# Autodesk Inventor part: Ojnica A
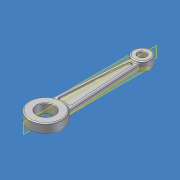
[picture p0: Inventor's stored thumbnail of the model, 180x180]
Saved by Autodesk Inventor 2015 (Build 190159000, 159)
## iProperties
Created: 2009-03
Part Number: Ojnica A
Document SubType Name: Modeling
Designer: Skola
Material: Všeobecné
Density: 1 g/cm^3
Mass: 13.4825 g
Surface Area: 73.0782 cm^2
Volume: 13.4825 cm^3
Appearance: Výchozí
Author: Skola
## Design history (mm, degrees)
sketch "Náčrt1"
  geometry: L1 (-69.019, -110.641)-(-63.941, -31.492); L2 (-53.491, -31.492)-(-48.413, -110.641); C1 r 4 at (-58.716, -24.164); C2 r 9 at (-58.716, -124.164); A1 r 17 centre (-58.716, -124.164) between (-69.019, -110.641) and (-48.413, -110.641); A2 r 9 centre (-58.716, -24.164) between (-53.491, -31.492) and (-63.941, -31.492)
  constraints: 4 centre point, 4 end point, 4 point on circle, 2 coincident
  dimensions: "d0" = 34 diameter of A1; "d1" = 18 diameter of A2; "d2" = 8 diameter of C1; "d3" = 18 diameter of C2; "d4" = 100 distance of A1.centre A2.centre
extrude "Vysunutí1" new body sketch "Náčrt1" distance "d5" = 6; taper "d6" = 0 deg
sketch "Náčrt2"
  geometry: C1 r 9 at (-58.716, -124.164) reference; C2 r 4 at (-58.716, -24.164) reference; C3 r 9 at (-58.716, -24.164); C4 r 17 at (-58.716, -124.164); A1 r 17 centre (-58.716, -124.164) between (-69.019, -110.641) and (-48.413, -110.641) reference; A2 r 9 centre (-58.716, -24.164) between (-53.491, -31.492) and (-63.941, -31.492) reference
  constraints: 2 centre point, 2 coincident, 2 concentric
extrude "Vysunutí2" join sketch "Náčrt2" distance "d7" = 2; taper "d8" = 0 deg
sketch "Náčrt3"
  geometry: C1 r 9 at (58.716, -124.164) reference; C2 r 4 at (58.716, -24.164) reference; C3 r 9 at (58.716, -24.164); C4 r 17 at (58.716, -124.164); A1 r 17 centre (58.716, -124.164) between (48.413, -110.641) and (69.019, -110.641) reference; A2 r 9 centre (58.716, -24.164) between (63.941, -31.492) and (53.491, -31.492) reference
  constraints: 2 centre point, 2 coincident, 2 concentric
  dimensions: "d9" = 34 diameter of C4 (derived)
extrude "Vysunutí3" join sketch "Náčrt3" distance "d10" = 2; taper "d11" = 0 deg
sketch "Náčrt6"
  geometry: L1 (-69.019, -110.641)-(-63.941, -31.492) reference; L2 (-53.491, -31.492)-(-48.413, -110.641) reference; L3 (-65.561, -103.603)-(-61.29, -37.023); L4 (-51.871, -103.603)-(-56.142, -37.023); A1 r 9 centre (-58.716, -24.164) between (-63.941, -31.492) and (-53.491, -31.492) reference; A2 r 17 centre (-58.716, -124.164) between (-48.413, -110.641) and (-69.019, -110.641) reference; A3 r 19 centre (-58.716, -124.164) between (-54.329, -105.677) and (-63.103, -105.677); A4 r 11 centre (-58.716, -24.164) between (-59.205, -35.153) and (-58.227, -35.153); A5 r 2 centre (-63.565, -103.731) between (-65.561, -103.603) and (-63.103, -105.677); A6 r 2 centre (-53.867, -103.731) between (-54.329, -105.677) and (-51.871, -103.603); A7 r 2 centre (-59.294, -37.151) between (-59.205, -35.153) and (-61.29, -37.023); A8 r 2 centre (-58.138, -37.151) between (-56.142, -37.023) and (-58.227, -35.153)
  constraints: 12 point on circle, 8 tangent, 6 centre point, 4 end point, 3 equal radius, 2 coincident, 2 parallel
  dimensions: "d25" = 3 distance between parallel lines of L3 L1; "d26" = 3 distance between parallel lines of L2 L4; "d27" = 38 diameter of A3; "d28" = 22 diameter of A4; "d29" = 2 radius of A5
extrude "Vysunutí6" cut sketch "Náčrt6" distance "d30" = 1.5; taper "d31" = 0 deg
node "Pracovní rovina1"
mirror "Zrcadlit1"
fillet "Zaoblení4" dims "d34" = 1
fillet "Zaoblení5" dims "d35" = 1
fillet "Zaoblení6" dims "d36" = 1
fillet "Zaoblení7" dims "d37" = 1
fillet "Zaoblení8" dims "d38" = 0.5
chamfer "Zkosení1" distance "d39" = 0.5; stored, may be unused: second distance "d40" = 2, angle "d41" = 45 deg
node "Pracovní rovina2"
node "Pracovní rovina3"
fillet "Zaoblení9" dims "d43" = 0.5
node "Těleso1"
node "Objemová tělesa"
node "Povrchová tělesa"
other parameters: "d32" = -3, "d42" = -17
